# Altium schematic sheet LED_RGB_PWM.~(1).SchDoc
size A4
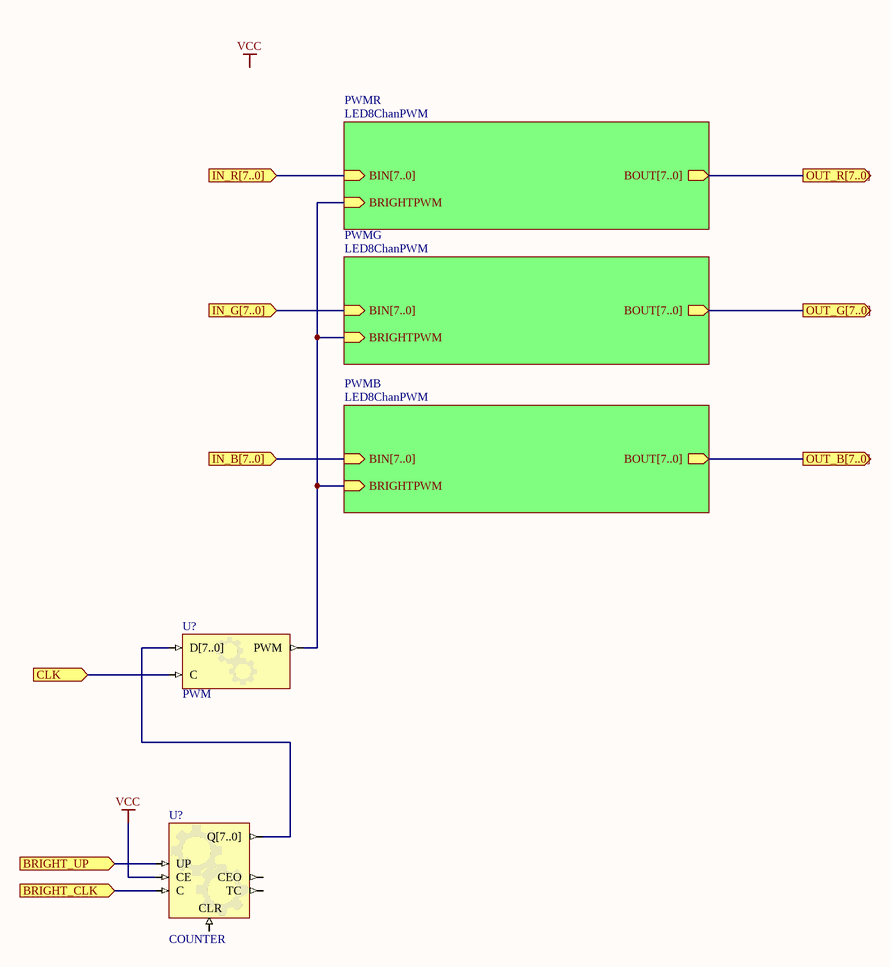
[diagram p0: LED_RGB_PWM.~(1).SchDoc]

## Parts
(Parts that share a designator on the sheet are numbered #1, #2 ... from top to bottom, then left to right.)
U?#1  PWM
U?#2  COUNTER

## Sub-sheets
PWMB = LED8ChanPWM: BIN[7..0] (in), BOUT[7..0] (out), BRIGHTPWM (in)
PWMG = LED8ChanPWM: BIN[7..0] (in), BOUT[7..0] (out), BRIGHTPWM (in)
PWMR = LED8ChanPWM: BIN[7..0] (in), BOUT[7..0] (out), BRIGHTPWM (in)

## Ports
BRIGHT_CLK (in), BRIGHT_UP (in), CLK (in), IN_B[7..0] (in), IN_G[7..0] (in), IN_R[7..0] (in), OUT_B[7..0] (out), OUT_G[7..0] (out), OUT_R[7..0] (out)

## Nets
VCC: U?#2.CE
BRIGHT_CLK: U?#2.C ; port BRIGHT_CLK
BRIGHT_UP: U?#2.UP ; port BRIGHT_UP
CLK: U?#1.C ; port CLK
NetU?#1_PWM: U?#1.PWM ; sheet PWMR/BRIGHTPWM, sheet PWMG/BRIGHTPWM, sheet PWMB/BRIGHTPWM

Not connected (* = marked no-connect by the designer): U?#1 D[7..0]; U?#2 CEO CLR Q[7..0] TC

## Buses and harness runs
bus port IN_B[7..0] = sheet PWMB/BIN[7..0]
bus port IN_G[7..0] = sheet PWMG/BIN[7..0]
bus port IN_R[7..0] = sheet PWMR/BIN[7..0]
bus port OUT_B[7..0] = sheet PWMB/BOUT[7..0]
bus port OUT_G[7..0] = sheet PWMG/BOUT[7..0]
bus port OUT_R[7..0] = sheet PWMR/BOUT[7..0]

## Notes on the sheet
- Labels drawn without touching a wire or pin: VCC

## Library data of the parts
U?#1 = PWM: Configurable PWM; ConfiguratorName: GENERIC_PWM; ConfigurationParameters: {}Version[1.0]{}Width[8]{}Prescaler[1]{}
U?#2 = COUNTER: Configurable Counter; ConfiguratorName: GENERIC_COUNTER; ConfigurationParameters: {}Version[1.0]{}Type[Binary]{}SyncReset[False]{}NegativeClockEdge[False]{}FixedDirection[False]{}IsIncrement[False]{}SignalWidth[8]{}MaxValue[255]{}BusOutput[True]{}Loadable[False]{}BusInput[False]{}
